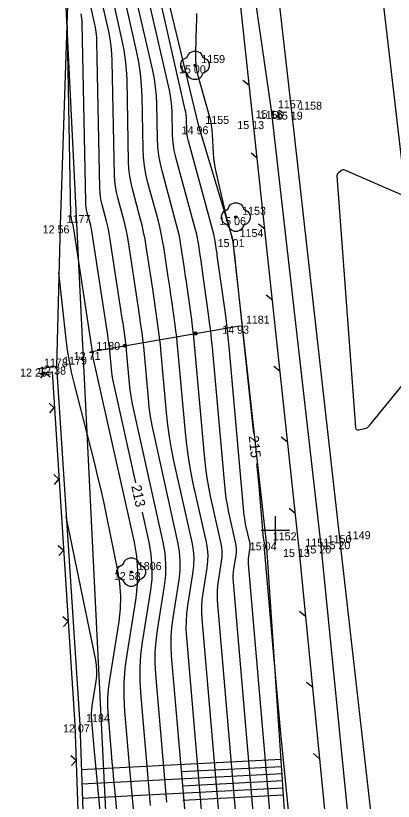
# Model space of a CAD drawing. Extents: x -711234 to -710007, y -1026313 to -1025448.
# Drawn here: x -710934.08 to -710920.87, y -1025784.48 to -1025756.99 of the extents above; entities that cross this region are included whole.
import ezdxf

# ---------------------------------------------------------------- set-up
doc = ezdxf.new("R2010")
doc.units = 0
for name, color, linetype in [('Ex_Contour Labels', 7, 'Continuous'), ('Ex_Major Contours', 7, 'Continuous'), ('Ex_Minor Contours', 7, 'Continuous'), ('Z_body', 7, 'Continuous'), ('Z_body_cisla', 7, 'Continuous'), ('Z_body_vysky_redukovane', 7, 'Continuous'), ('Z_hektometricka_sit', 7, 'Continuous'), ('Z_hrany_paty', 7, 'Continuous'), ('Z_katastr_hranice', 7, 'Continuous'), ('Z_komunikace', 7, 'Continuous'), ('Z_ploty', 7, 'Continuous'), ('Z_ploty_znacky', 7, 'Continuous'), ('Z_svodidla', 7, 'Continuous'), ('Z_svodidla_znacky', 7, 'Continuous'), ('Z_technicke_srafy', 7, 'Continuous'), ('Z_vdz12_plna', 7, 'Continuous'), ('Z_vdz25_plna', 7, 'Continuous'), ('Z_zabradli', 7, 'Continuous'), ('Z_zabradli_znaky', 7, 'Continuous'), ('Z_zelen_jednotliva', 7, 'Continuous')]:
    doc.layers.add(name, color=color, linetype=linetype)

# ---------------------------------------------------------------- blocks, each defined once
blk = doc.blocks.new('POINT_DISPLAY')
blk.add_line((0, 0), (0, 0))
blk = doc.blocks.new('Z24')
for p, q in [((-0.42, 0.2), (-0.28, 0.28)), ((-0.28, 0.28), (-0.23, 0.38)), ((-0.23, 0.38), (-0.17, 0.45)), ((-0.17, 0.45), (-0.05, 0.5)), ((-0.05, 0.5), (0.05, 0.5)), ((0.05, 0.5), (0.17, 0.45)), ((0.17, 0.45), (0.23, 0.38)), ((0.23, 0.38), (0.28, 0.28)), ((0.28, 0.28), (0.42, 0.2)), ((-0.5, 0.05), (-0.47, 0.13)), ((-0.5, -0.05), (-0.5, 0.05)), ((-0.47, 0.13), (-0.42, 0.2)), ((-0.03, -0.03), (-0.03, 0.03)), ((-0.03, 0.03), (0.03, 0.03)), ((0.03, 0.03), (0.03, -0.03)), ((0.42, 0.2), (0.47, 0.13)), ((0.47, 0.13), (0.5, 0.05)), ((0.5, 0.05), (0.5, -0.05)), ((-0.45, -0.17), (-0.5, -0.05)), ((-0.38, -0.23), (-0.45, -0.17)), ((-0.28, -0.28), (-0.38, -0.23)), ((0.03, -0.03), (-0.03, -0.03)), ((0.38, -0.23), (0.28, -0.28)), ((0.45, -0.17), (0.38, -0.23)), ((0.5, -0.05), (0.45, -0.17)), ((-0.2, -0.42), (-0.28, -0.28)), ((-0.13, -0.47), (-0.2, -0.42)), ((-0.05, -0.5), (-0.13, -0.47)), ((0.05, -0.5), (-0.05, -0.5)), ((0.13, -0.47), (0.05, -0.5)), ((0.2, -0.42), (0.13, -0.47)), ((0.28, -0.28), (0.2, -0.42))]:
    blk.add_line(p, q)
blk = doc.blocks.new('Z212')
for p, q in [((-0.17, 0.17), (0, 0)), ((0, 0), (0.17, 0.17))]:
    blk.add_line(p, q)
blk = doc.blocks.new('Z529')
blk.add_line((0, 0), (0.2, 0.2))
blk = doc.blocks.new('Z530')
for p, q in [((-0.05, 0.03), (-0.03, 0.05)), ((-0.05, -0.03), (-0.05, 0.03)), ((-0.03, 0.05), (0.03, 0.05)), ((-0.03, -0.03), (-0.03, 0.03)), ((-0.03, 0.03), (0.03, 0.03)), ((-0.03, -0.03), (0.03, 0.03)), ((0.03, 0.05), (0.05, 0.03)), ((0.03, 0.03), (0.03, -0.03)), ((0.05, 0.03), (0.05, -0.03)), ((-0.03, -0.05), (-0.05, -0.03)), ((0.03, -0.03), (-0.03, -0.03)), ((0.03, -0.05), (-0.03, -0.05)), ((0.05, -0.03), (0.03, -0.05))]:
    blk.add_line(p, q)

msp = doc.modelspace()

# ---------------------------------------------------------------- linework, layer by layer
at = {"layer": 'Ex_Major Contours'}
for points in [[(-710926.721, -1025787.851), (-710927.558, -1025778.102), (-710927.57, -1025777.877), (-710927.569, -1025777.652), (-710927.554, -1025777.427), (-710927.525, -1025777.203), (-710927.381, -1025776.307), (-710927.356, -1025776.084), (-710927.352, -1025775.861), (-710927.37, -1025775.639), (-710927.408, -1025775.417), (-710927.879, -1025773.3), (-710927.967, -1025772.873), (-710928.04, -1025772.443), (-710928.1, -1025772.011), (-710928.146, -1025771.577), (-710928.407, -1025768.648), (-710928.428, -1025768.437), (-710928.45, -1025768.226), (-710928.476, -1025768.015), (-710928.504, -1025767.805), (-710928.621, -1025766.965), (-710928.651, -1025766.755), (-710928.681, -1025766.545), (-710928.712, -1025766.335), (-710928.744, -1025766.125), (-710928.901, -1025765.095), (-710928.941, -1025764.854), (-710928.988, -1025764.615), (-710929.041, -1025764.377), (-710929.102, -1025764.14), (-710929.454, -1025762.839), (-710929.525, -1025762.542), (-710929.577, -1025762.243), (-710929.611, -1025761.941), (-710929.626, -1025761.636), (-710929.661, -1025759.823), (-710929.68, -1025759.42), (-710929.718, -1025759.019), (-710929.777, -1025758.621), (-710929.856, -1025758.226), (-710930.256, -1025756.462)], [(-710931.805, -1025756.928), (-710931.789, -1025757.01), (-710931.777, -1025757.092), (-710931.769, -1025757.175), (-710931.765, -1025757.259), (-710931.643, -1025763.507), (-710931.638, -1025763.6), (-710931.628, -1025763.692), (-710931.612, -1025763.784), (-710931.59, -1025763.874), (-710931.492, -1025764.236), (-710931.469, -1025764.326), (-710931.449, -1025764.417), (-710931.431, -1025764.509), (-710931.415, -1025764.601), (-710930.873, -1025768.168), (-710930.866, -1025768.215), (-710930.859, -1025768.262), (-710930.852, -1025768.309), (-710930.845, -1025768.356), (-710930.819, -1025768.545), (-710930.812, -1025768.593), (-710930.807, -1025768.64), (-710930.802, -1025768.687), (-710930.797, -1025768.735), (-710930.742, -1025769.352), (-710930.729, -1025769.47), (-710930.713, -1025769.588), (-710930.693, -1025769.705), (-710930.669, -1025769.821), (-710929.886, -1025773.343)], [(-710927.756, -1025756.911), (-710927.76, -1025757.139), (-710927.766, -1025757.366), (-710927.795, -1025758.275), (-710927.794, -1025758.502), (-710927.776, -1025758.726), (-710927.74, -1025758.948), (-710927.687, -1025759.168), (-710927.312, -1025760.501), (-710927.272, -1025760.66), (-710927.241, -1025760.821), (-710927.219, -1025760.983), (-710927.206, -1025761.146), (-710927.171, -1025761.803), (-710927.159, -1025761.967), (-710927.14, -1025762.13), (-710927.113, -1025762.292), (-710927.08, -1025762.453), (-710926.764, -1025763.821), (-710926.74, -1025763.92), (-710926.716, -1025764.02), (-710926.691, -1025764.118), (-710926.665, -1025764.217), (-710926.506, -1025764.803), (-710926.504, -1025764.813), (-710926.501, -1025764.832), (-710926.464, -1025765.098), (-710926.458, -1025765.144), (-710926.452, -1025765.189), (-710926.447, -1025765.234), (-710926.442, -1025765.28), (-710925.764, -1025771.613)], [(-710925.655, -1025772.658), (-710925.655, -1025772.664), (-710925.623, -1025772.994), (-710925.593, -1025773.324), (-710925.419, -1025775.272), (-710925.417, -1025775.289), (-710925.415, -1025775.305), (-710925.412, -1025775.322), (-710925.409, -1025775.338), (-710925.391, -1025775.42), (-710925.389, -1025775.428), (-710925.389, -1025775.437), (-710925.389, -1025775.446), (-710925.39, -1025775.454), (-710925.395, -1025775.489), (-710925.396, -1025775.497), (-710925.397, -1025775.506), (-710925.397, -1025775.514), (-710925.396, -1025775.523), (-710925.064, -1025779.395), (-710925.008, -1025780.043), (-710924.949, -1025780.69), (-710924.888, -1025781.338), (-710924.825, -1025781.985), (-710923.835, -1025791.963)], [(-710929.658, -1025774.368), (-710929.425, -1025775.414), (-710929.35, -1025775.849), (-710929.316, -1025776.285), (-710929.324, -1025776.722), (-710929.373, -1025777.161), (-710929.655, -1025778.917), (-710929.711, -1025779.357), (-710929.741, -1025779.797), (-710929.744, -1025780.239), (-710929.719, -1025780.682), (-710929.44, -1025783.934), (-710929.38, -1025784.624)]]:
    msp.add_lwpolyline(points, dxfattribs=at)
at = {"layer": 'Ex_Minor Contours'}
for points in [[(-710927.428, -1025786.56), (-710928.098, -1025778.747), (-710928.114, -1025778.467), (-710928.112, -1025778.188), (-710928.093, -1025777.909), (-710928.057, -1025777.631), (-710927.879, -1025776.521), (-710927.848, -1025776.243), (-710927.843, -1025775.967), (-710927.865, -1025775.691), (-710927.912, -1025775.416), (-710928.546, -1025772.567), (-710928.632, -1025772.149), (-710928.704, -1025771.728), (-710928.763, -1025771.306), (-710928.807, -1025770.882), (-710929.005, -1025768.67), (-710929.021, -1025768.499), (-710929.039, -1025768.329), (-710929.06, -1025768.16), (-710929.083, -1025767.99), (-710929.177, -1025767.313), (-710929.201, -1025767.143), (-710929.226, -1025766.974), (-710929.251, -1025766.805), (-710929.276, -1025766.636), (-710929.515, -1025765.063), (-710929.557, -1025764.814), (-710929.605, -1025764.566), (-710929.661, -1025764.32), (-710929.724, -1025764.075), (-710929.988, -1025763.098), (-710930.047, -1025762.853), (-710930.09, -1025762.605), (-710930.118, -1025762.355), (-710930.13, -1025762.104), (-710930.187, -1025759.223), (-710930.202, -1025758.879), (-710930.235, -1025758.538), (-710930.285, -1025758.198), (-710930.353, -1025757.861), (-710930.662, -1025756.496)], [(-710926.015, -1025789.142), (-710927.017, -1025777.458), (-710927.027, -1025777.286), (-710927.026, -1025777.115), (-710927.014, -1025776.945), (-710926.992, -1025776.774), (-710926.883, -1025776.094), (-710926.864, -1025775.924), (-710926.861, -1025775.755), (-710926.874, -1025775.586), (-710926.904, -1025775.418), (-710927.261, -1025773.81), (-710927.328, -1025773.485), (-710927.384, -1025773.159), (-710927.43, -1025772.83), (-710927.464, -1025772.501), (-710927.81, -1025768.626), (-710927.834, -1025768.374), (-710927.861, -1025768.123), (-710927.892, -1025767.871), (-710927.925, -1025767.62), (-710928.085, -1025766.479), (-710928.11, -1025766.297), (-710928.137, -1025766.115), (-710928.163, -1025765.933), (-710928.191, -1025765.752), (-710928.301, -1025765.025), (-710928.332, -1025764.843), (-710928.367, -1025764.663), (-710928.407, -1025764.484), (-710928.453, -1025764.306), (-710928.951, -1025762.464), (-710929.021, -1025762.174), (-710929.072, -1025761.881), (-710929.105, -1025761.586), (-710929.119, -1025761.289), (-710929.143, -1025760.093), (-710929.156, -1025759.795), (-710929.185, -1025759.499), (-710929.228, -1025759.204), (-710929.287, -1025758.912), (-710929.85, -1025756.428)], [(-710929.444, -1025756.394), (-710928.718, -1025759.598), (-710928.68, -1025759.787), (-710928.651, -1025759.978), (-710928.633, -1025760.17), (-710928.624, -1025760.363), (-710928.609, -1025761.138), (-710928.599, -1025761.331), (-710928.578, -1025761.522), (-710928.545, -1025761.711), (-710928.5, -1025761.899), (-710927.804, -1025764.472), (-710927.773, -1025764.591), (-710927.746, -1025764.712), (-710927.723, -1025764.832), (-710927.702, -1025764.954), (-710927.628, -1025765.442), (-710927.61, -1025765.564), (-710927.592, -1025765.686), (-710927.574, -1025765.808), (-710927.557, -1025765.93), (-710927.346, -1025767.435), (-710927.308, -1025767.727), (-710927.272, -1025768.019), (-710927.241, -1025768.312), (-710927.213, -1025768.605), (-710926.783, -1025773.425), (-710926.759, -1025773.65), (-710926.728, -1025773.874), (-710926.689, -1025774.097), (-710926.644, -1025774.319), (-710926.399, -1025775.418), (-710926.379, -1025775.534), (-710926.37, -1025775.649), (-710926.372, -1025775.765), (-710926.386, -1025775.881), (-710926.46, -1025776.346), (-710926.475, -1025776.462), (-710926.483, -1025776.579), (-710926.484, -1025776.696), (-710926.477, -1025776.813), (-710925.309, -1025790.433)], [(-710924.602, -1025791.724), (-710925.937, -1025776.168), (-710925.94, -1025776.105), (-710925.94, -1025776.042), (-710925.936, -1025775.98), (-710925.928, -1025775.917), (-710925.888, -1025775.667), (-710925.881, -1025775.605), (-710925.879, -1025775.543), (-710925.884, -1025775.481), (-710925.895, -1025775.419), (-710926.026, -1025774.829), (-710926.051, -1025774.71), (-710926.071, -1025774.59), (-710926.088, -1025774.469), (-710926.101, -1025774.348), (-710926.615, -1025768.583), (-710926.647, -1025768.249), (-710926.683, -1025767.916), (-710926.723, -1025767.583), (-710926.768, -1025767.25), (-710927.029, -1025765.381), (-710927.038, -1025765.319), (-710927.047, -1025765.257), (-710927.056, -1025765.194), (-710927.065, -1025765.132), (-710927.103, -1025764.883), (-710927.113, -1025764.821), (-710927.126, -1025764.76), (-710927.139, -1025764.699), (-710927.155, -1025764.638), (-710928.049, -1025761.334), (-710928.069, -1025761.249), (-710928.085, -1025761.162), (-710928.094, -1025761.075), (-710928.099, -1025760.987), (-710928.106, -1025760.633), (-710928.11, -1025760.545), (-710928.118, -1025760.457), (-710928.131, -1025760.37), (-710928.148, -1025760.284), (-710929.038, -1025756.361)], [(-710928.795, -1025784.51), (-710929.179, -1025780.037), (-710929.2, -1025779.648), (-710929.198, -1025779.261), (-710929.172, -1025778.874), (-710929.122, -1025778.489), (-710928.875, -1025776.947), (-710928.832, -1025776.563), (-710928.825, -1025776.179), (-710928.855, -1025775.796), (-710928.921, -1025775.415), (-710929.961, -1025770.737), (-710930.006, -1025770.519), (-710930.044, -1025770.301), (-710930.074, -1025770.082), (-710930.097, -1025769.862), (-710930.2, -1025768.713), (-710930.208, -1025768.625), (-710930.218, -1025768.536), (-710930.228, -1025768.448), (-710930.24, -1025768.36), (-710930.289, -1025768.009), (-710930.302, -1025767.921), (-710930.314, -1025767.833), (-710930.327, -1025767.745), (-710930.34, -1025767.657), (-710930.782, -1025764.755), (-710930.806, -1025764.611), (-710930.834, -1025764.467), (-710930.866, -1025764.324), (-710930.903, -1025764.182), (-710931.056, -1025763.616), (-710931.09, -1025763.473), (-710931.115, -1025763.33), (-710931.131, -1025763.185), (-710931.138, -1025763.039), (-710931.239, -1025757.913), (-710931.246, -1025757.743), (-710931.263, -1025757.574), (-710931.288, -1025757.406), (-710931.321, -1025757.239), (-710931.474, -1025756.564)], [(-710931.068, -1025756.53), (-710930.837, -1025757.55), (-710930.786, -1025757.802), (-710930.749, -1025758.056), (-710930.724, -1025758.311), (-710930.713, -1025758.568), (-710930.634, -1025762.571), (-710930.624, -1025762.77), (-710930.602, -1025762.967), (-710930.568, -1025763.163), (-710930.522, -1025763.357), (-710930.313, -1025764.128), (-710930.264, -1025764.322), (-710930.22, -1025764.516), (-710930.181, -1025764.712), (-710930.149, -1025764.909), (-710929.808, -1025767.146), (-710929.789, -1025767.275), (-710929.77, -1025767.403), (-710929.751, -1025767.532), (-710929.733, -1025767.661), (-710929.661, -1025768.175), (-710929.644, -1025768.304), (-710929.629, -1025768.433), (-710929.615, -1025768.562), (-710929.602, -1025768.691), (-710929.452, -1025770.372), (-710929.418, -1025770.694), (-710929.374, -1025771.015), (-710929.319, -1025771.334), (-710929.254, -1025771.652), (-710928.417, -1025775.416), (-710928.36, -1025775.744), (-710928.334, -1025776.073), (-710928.34, -1025776.403), (-710928.377, -1025776.734), (-710928.59, -1025778.06), (-710928.633, -1025778.392), (-710928.655, -1025778.724), (-710928.657, -1025779.058), (-710928.639, -1025779.392), (-710928.134, -1025785.269)], [(-710929.95, -1025784.87), (-710929.997, -1025784.366), (-710930.041, -1025783.862), (-710930.085, -1025783.358), (-710930.26, -1025781.326), (-710930.287, -1025780.829), (-710930.284, -1025780.334), (-710930.251, -1025779.839), (-710930.187, -1025779.346), (-710929.871, -1025777.374), (-710929.816, -1025776.882), (-710929.807, -1025776.391), (-710929.845, -1025775.902), (-710929.93, -1025775.414), (-710931.377, -1025768.906), (-710931.38, -1025768.89), (-710931.383, -1025768.874), (-710931.385, -1025768.858), (-710931.387, -1025768.842), (-710931.394, -1025768.757), (-710931.396, -1025768.743), (-710931.397, -1025768.73), (-710931.403, -1025768.691), (-710931.405, -1025768.678), (-710932.049, -1025764.447), (-710932.055, -1025764.407), (-710932.063, -1025764.368), (-710932.072, -1025764.328), (-710932.082, -1025764.289), (-710932.124, -1025764.133), (-710932.133, -1025764.094), (-710932.14, -1025764.055), (-710932.145, -1025764.015), (-710932.147, -1025763.975), (-710932.283, -1025757.015)], [(-710918.07, -1025764.358), (-710922.567, -1025762.4), (-710922.598, -1025762.39), (-710922.627, -1025762.389), (-710922.656, -1025762.396), (-710922.683, -1025762.411), (-710922.793, -1025762.488), (-710922.817, -1025762.509), (-710922.833, -1025762.533), (-710922.842, -1025762.561), (-710922.843, -1025762.593), (-710922.192, -1025771.402), (-710922.183, -1025771.446), (-710922.161, -1025771.475), (-710922.127, -1025771.487), (-710922.082, -1025771.484), (-710921.875, -1025771.438), (-710921.826, -1025771.422), (-710921.781, -1025771.4), (-710921.741, -1025771.37), (-710921.705, -1025771.333), (-710917.598, -1025766.304)], [(-710929.452, -1025796.343), (-710930.615, -1025784.056), (-710930.645, -1025783.738), (-710930.674, -1025783.419), (-710930.703, -1025783.1), (-710930.73, -1025782.781), (-710930.84, -1025781.506), (-710930.857, -1025781.187), (-710930.856, -1025780.869), (-710930.834, -1025780.552), (-710930.793, -1025780.236), (-710930.465, -1025778.189), (-710930.414, -1025777.743), (-710930.404, -1025777.298), (-710930.434, -1025776.854), (-710930.504, -1025776.41), (-710930.894, -1025774.512), (-710930.991, -1025774.049), (-710931.095, -1025773.586), (-710931.203, -1025773.126), (-710931.317, -1025772.666), (-710932.036, -1025769.842), (-710932.125, -1025769.462), (-710932.201, -1025769.08), (-710932.264, -1025768.695), (-710932.314, -1025768.308), (-710932.57, -1025765.977)], [(-710929.989, -1025796.865), (-710931.327, -1025782.739), (-710931.34, -1025782.605), (-710931.352, -1025782.472), (-710931.364, -1025782.338), (-710931.376, -1025782.205), (-710931.421, -1025781.671), (-710931.429, -1025781.538), (-710931.428, -1025781.405), (-710931.419, -1025781.272), (-710931.402, -1025781.139), (-710931.265, -1025780.283), (-710931.243, -1025780.096), (-710931.239, -1025779.91), (-710931.251, -1025779.724), (-710931.281, -1025779.538), (-710932.31, -1025774.52)]]:
    msp.add_lwpolyline(points, dxfattribs=at)
at = {"layer": 'Z_hektometricka_sit'}
for p, q in [((-710925, -1025774.5), (-710925, -1025775.5)), ((-710925.5, -1025775), (-710924.5, -1025775))]:
    msp.add_line(p, q, dxfattribs=at)
at = {"layer": 'Z_hrany_paty'}
for p, q in [((-710927.67, -1025760.86), (-710929.1, -1025754.92)), ((-710932.27, -1025756.63), (-710932.53, -1025764.33)), ((-710926.48, -1025764.81), (-710927.67, -1025760.86)), ((-710932.53, -1025764.33), (-710932.65, -1025769.27)), ((-710925.31, -1025775.42), (-710926.48, -1025764.81)), ((-710924.15, -1025792.55), (-710925.31, -1025775.42))]:
    msp.add_line(p, q, dxfattribs=at)
at = {"layer": 'Z_katastr_hranice'}
msp.add_lwpolyline([(-710937.26, -1025842.82), (-710936.45, -1025842.11), (-710935.96, -1025842), (-710933.08, -1025840.66), (-710931.05, -1025838.78), (-710930.88, -1025838.46), (-710929.59, -1025835.96), (-710928.58, -1025832.31), (-710932.7, -1025748.89), (-710932.82, -1025746.51)], dxfattribs=at)
at = {"layer": 'Z_komunikace'}
for p, q in [((-710925.13, -1025760.3), (-710926.82, -1025748.72)), ((-710923.4, -1025775.53), (-710925.13, -1025760.3)), ((-710921.81, -1025791.37), (-710923.4, -1025775.53))]:
    msp.add_line(p, q, dxfattribs=at)
at = {"layer": 'Z_ploty'}
for p, q in [((-710933.32, -1025769.34), (-710932.65, -1025769.27)), ((-710932.65, -1025769.27), (-710931.84, -1025781.79)), ((-710933.3, -1025769.51), (-710932.81, -1025769.46)), ((-710932.81, -1025769.46), (-710932.01, -1025781.8)), ((-710932.01, -1025781.8), (-710931.45, -1025798.13)), ((-710931.84, -1025781.79), (-710931.28, -1025798.12))]:
    msp.add_line(p, q, dxfattribs=at)
at = {"layer": 'Z_svodidla'}
for p, q in [((-710925.77, -1025760.68), (-710927.3, -1025746.72)), ((-710924.17, -1025775.65), (-710925.77, -1025760.68)), ((-710922.59, -1025791.7), (-710924.17, -1025775.65))]:
    msp.add_line(p, q, dxfattribs=at)
at = {"layer": 'Z_technicke_srafy'}
for p, q in [((-710924.8, -1025783.02), (-710931.79, -1025783.38)), ((-710924.78, -1025783.27), (-710928.28, -1025783.45)), ((-710924.76, -1025783.52), (-710931.77, -1025783.88)), ((-710924.74, -1025783.77), (-710928.25, -1025783.95)), ((-710924.73, -1025784.02), (-710931.75, -1025784.38)), ((-710924.71, -1025784.27), (-710928.23, -1025784.45))]:
    msp.add_line(p, q, dxfattribs=at)
at = {"layer": 'Z_vdz12_plna'}
msp.add_line((-710921.81, -1025751.6), (-710920.24, -1025765.07), dxfattribs=at)
at = {"layer": 'Z_vdz25_plna'}
for p, q in [((-710924.42, -1025760.35), (-710925.96, -1025746.9)), ((-710922.73, -1025775.38), (-710924.42, -1025760.35)), ((-710920.93, -1025791.32), (-710922.73, -1025775.38))]:
    msp.add_line(p, q, dxfattribs=at)
at = {"layer": 'Z_zabradli'}
msp.add_line((-710931.49, -1025768.76), (-710926.25, -1025767.84), dxfattribs=at)

# ---------------------------------------------------------------- block references
at = {"layer": 'Z_body'}
for p in [(-710927.81, -1025758.73), (-710925.13, -1025760.3), (-710924.42, -1025760.35), (-710927.67, -1025760.86), (-710925.77, -1025760.68), (-710926.38, -1025764.04), (-710932.53, -1025764.33), (-710926.48, -1025764.81), (-710926.25, -1025767.84), (-710931.49, -1025768.76), (-710933.32, -1025769.34), (-710932.65, -1025769.27), (-710925.31, -1025775.42), (-710922.73, -1025775.38), (-710924.17, -1025775.65), (-710923.4, -1025775.53), (-710930.04, -1025776.46), (-710931.84, -1025781.79)]:
    msp.add_blockref('POINT_DISPLAY', p, dxfattribs=at)
at = {"layer": 'Z_ploty_znacky'}
for p, rotation in [((-710933.06, -1025769.49), -174.00000000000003), ((-710932.73, -1025770.71), 93.7), ((-710932.57, -1025773.21), 93.7), ((-710932.41, -1025775.7), 93.7), ((-710932.25, -1025778.19), 93.7), ((-710931.97, -1025783.05), 91.99999999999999)]:
    msp.add_blockref('Z212', p, dxfattribs=dict(at, rotation=rotation))
at = {"layer": 'Z_svodidla_znacky'}
for p, rotation in [((-710925.91, -1025759.44), 96.3), ((-710925.63, -1025761.98), 96.1), ((-710925.37, -1025764.46), 96.1), ((-710925.1, -1025766.95), 96.1), ((-710924.83, -1025769.44), 96.1), ((-710924.57, -1025771.92), 96.1), ((-710924.3, -1025774.41), 96.1), ((-710923.94, -1025778.02), 95.6), ((-710923.94, -1025778.02), 95.6), ((-710923.69, -1025780.5), 95.6), ((-710923.69, -1025780.5), 95.6), ((-710923.45, -1025782.99), 95.6), ((-710923.45, -1025782.99), 95.6)]:
    msp.add_blockref('Z529', p, dxfattribs=dict(at, rotation=rotation))
at = {"layer": 'Z_zabradli_znaky', "rotation": -170}
for p in [(-710927.8, -1025768.11), (-710930.26, -1025768.54)]:
    msp.add_blockref('Z530', p, dxfattribs=at)
at = {"layer": 'Z_zelen_jednotliva'}
for p in [(-710927.81, -1025758.73), (-710926.38, -1025764.04), (-710930.04, -1025776.46)]:
    msp.add_blockref('Z24', p, dxfattribs=at)

# ---------------------------------------------------------------- texts
at = {"layer": 'Ex_Contour Labels'}
for s, rotation, p in [('215', 275.948, (-710925.931, -1025771.703)), ('213', 282.5364, (-710930.041, -1025773.452))]:
    msp.add_text(s, height=0.35, rotation=rotation, dxfattribs=at).set_placement(p)
at = {"layer": 'Z_body_cisla'}
for s, p in [('1159', (-710927.59, -1025758.65)), ('1157', (-710924.91, -1025760.23)), ('1158', (-710924.2, -1025760.28)), ('1156', (-710925.55, -1025760.61)), ('1155', (-710927.45, -1025760.78)), ('1153', (-710926.16, -1025763.96)), ('1177', (-710932.3, -1025764.25)), ('1154', (-710926.25, -1025764.74)), ('1181', (-710926.03, -1025767.77)), ('1180', (-710931.26, -1025768.69)), ('1178', (-710933.09, -1025769.27)), ('1179', (-710932.42, -1025769.2)), ('1152', (-710925.09, -1025775.35)), ('1150', (-710923.17, -1025775.45)), ('1149', (-710922.5, -1025775.31)), ('1151', (-710923.95, -1025775.57)), ('1806', (-710929.81, -1025776.39)), ('1184', (-710931.62, -1025781.71))]:
    msp.add_text(s, height=0.28, dxfattribs=at).set_placement(p)
at = {"layer": 'Z_body_vysky_redukovane'}
for s, p in [('15 00', (-710928.37, -1025759.01)), ('15 18', (-710925.69, -1025760.58)), ('15 19', (-710924.98, -1025760.63)), ('14 96', (-710928.277, -1025761.14)), ('15 13', (-710926.33, -1025760.96)), ('15 06', (-710926.963, -1025764.32)), ('12 56', (-710933.137, -1025764.61)), ('15 01', (-710927.017, -1025765.09)), ('14 93', (-710926.857, -1025768.12)), ('12 71', (-710932.05, -1025769.04)), ('12 25', (-710933.927, -1025769.62)), ('12 38', (-710933.257, -1025769.55)), ('15 04', (-710925.893, -1025775.7)), ('15 20', (-710923.313, -1025775.66)), ('15 13', (-710924.73, -1025775.93)), ('15 20', (-710923.983, -1025775.81)), ('12 58', (-710930.647, -1025776.74)), ('12 07', (-710932.423, -1025782.07))]:
    msp.add_text(s, height=0.28, dxfattribs=at).set_placement(p)

doc.saveas('drawing.dxf')
